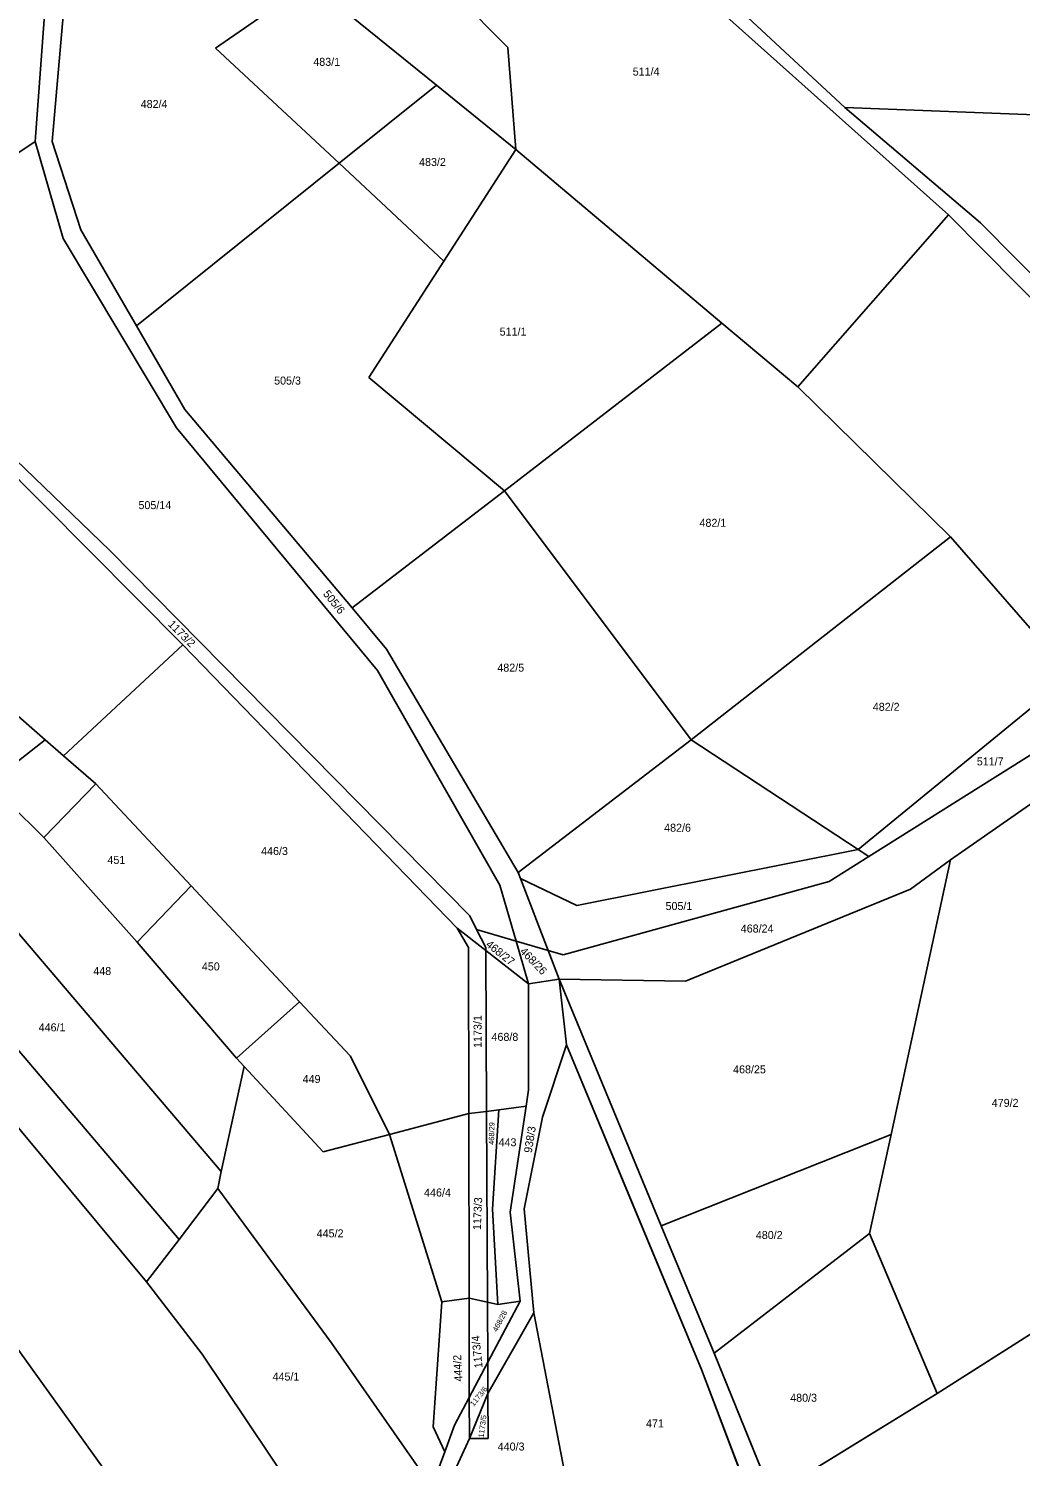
# Model space of a CAD drawing. Extents: x -593358 to -590116, y -1072518 to -1068420.
# Drawn here: x -591559.2 to -591348.6, y -1071926.1 to -1071622.8 of the extents above; entities that cross this region are included whole.
import ezdxf

# ---------------------------------------------------------------- set-up
doc = ezdxf.new("R2010")
doc.units = 0
for name, color, linetype in [('lesy', 7, 'Continuous'), ('Parcela KN', 7, 'Continuous'), ('Parcela ZE', 7, 'Continuous'), ('Parcelní číslo', 7, 'Continuous')]:
    doc.layers.add(name, color=color, linetype=linetype)

msp = doc.modelspace()

# ---------------------------------------------------------------- linework, layer by layer
at = {"layer": 'lesy'}
for points in [[(-591424.88, -1071877.07), (-591400.495, -1071867.39), (-591376.11, -1071857.71), (-591363.48, -1071799.36)], [(-591445.01, -1071838.65), (-591446.54, -1071824.7), (-591435.71, -1071850.885), (-591424.88, -1071877.07), (-591413.68, -1071904.15), (-591401.39, -1071934.26), (-591366.29, -1071912.68), (-591337.735, -1071894.515), (-591309.18, -1071876.35)], [(-591382.44, -1071994.17), (-591395.58, -1071962.26), (-591405.97, -1071934.935), (-591416.36, -1071907.61), (-591430.685, -1071873.13), (-591445.01, -1071838.65)]]:
    msp.add_lwpolyline(points, dxfattribs=at)
at = {"layer": 'Parcela KN'}
for p, q in [((-591457.44, -1071626.79), (-591488.65, -1071595.46)), ((-591411.6, -1071619.71), (-591363.88, -1071662.35)), ((-591385.94, -1071639.55), (-591408.48, -1071618.62)), ((-591455.76, -1071648.5), (-591457.44, -1071626.79)), ((-591357.12, -1071664.05), (-591385.94, -1071639.55)), ((-591471.03, -1071672.16), (-591455.76, -1071648.5)), ((-591363.88, -1071662.35), (-591275.95, -1071751.3)), ((-591338.4, -1071682.97), (-591357.12, -1071664.05)), ((-591486.97, -1071696.88), (-591471.03, -1071672.16)), ((-591526.45, -1071753.66), (-591589.09, -1071690.73)), ((-591542.01, -1071733.67), (-591587.76, -1071689.48)), ((-591458.15, -1071720.97), (-591486.97, -1071696.88)), ((-591418.58, -1071773.83), (-591458.15, -1071720.97)), ((-591465.57, -1071811.27), (-591542.01, -1071733.67)), ((-591468.22, -1071813.85), (-591526.45, -1071753.66)), ((-591332.39, -1071768.16), (-591380.82, -1071798.64)), ((-591383.05, -1071797.18), (-591418.58, -1071773.83)), ((-591329.09, -1071775.34), (-591363.48, -1071799.36)), ((-591380.82, -1071798.64), (-591383.05, -1071797.18)), ((-591380.82, -1071798.64), (-591389.26, -1071803.95)), ((-591376.11, -1071857.71), (-591363.48, -1071799.36)), ((-591389.26, -1071803.95), (-591445.72, -1071819.56)), ((-591464.12, -1071814.13), (-591465.57, -1071811.27)), ((-591534.18, -1071888.97), (-591595.89, -1071814.9)), ((-591468.22, -1071813.85), (-591465.86, -1071818)), ((-591462.16, -1071817.99), (-591464.12, -1071814.13)), ((-591455.71, -1071816.61), (-591464.12, -1071814.13)), ((-591465.86, -1071818), (-591465.79, -1071853.26)), ((-591462.16, -1071818.58), (-591462.16, -1071817.99)), ((-591448.88, -1071818.63), (-591455.71, -1071816.61)), ((-591461.99, -1071852.77), (-591462.16, -1071818.58)), ((-591445.72, -1071819.56), (-591448.88, -1071818.63)), ((-591446.54, -1071824.7), (-591453.07, -1071825.68)), ((-591453.07, -1071825.68), (-591453.07, -1071848.23)), ((-591424.88, -1071877.07), (-591446.54, -1071824.7)), ((-591445.01, -1071838.65), (-591446.54, -1071824.7)), ((-591450.12, -1071854.04), (-591445.01, -1071838.65)), ((-591416.36, -1071907.61), (-591445.01, -1071838.65)), ((-591453.07, -1071848.23), (-591453.6, -1071851.69)), ((-591453.6, -1071851.69), (-591457.01, -1071874.19)), ((-591465.79, -1071853.26), (-591465.71, -1071892.42)), ((-591461.78, -1071893.31), (-591461.99, -1071852.77)), ((-591454.01, -1071873.48), (-591450.12, -1071854.04)), ((-591376.11, -1071857.71), (-591424.88, -1071877.07)), ((-591380.65, -1071878.72), (-591376.11, -1071857.71)), ((-591457.01, -1071874.19), (-591454.86, -1071893.05)), ((-591451.95, -1071895.56), (-591454.01, -1071873.48)), ((-591413.68, -1071904.15), (-591424.88, -1071877.07)), ((-591380.65, -1071878.72), (-591413.68, -1071904.15)), ((-591366.29, -1071912.68), (-591380.65, -1071878.72)), ((-591366.29, -1071912.68), (-591309.18, -1071876.35)), ((-591522.4, -1071904.35), (-591534.18, -1071888.97)), ((-591465.71, -1071892.42), (-591465.66, -1071913.53)), ((-591461.72, -1071906.06), (-591461.78, -1071893.31)), ((-591454.86, -1071893.05), (-591461.72, -1071906.06)), ((-591451.95, -1071895.56), (-591461.69, -1071912.67)), ((-591445.06, -1071931.17), (-591451.95, -1071895.56)), ((-591500.54, -1071936.85), (-591522.4, -1071904.35)), ((-591461.69, -1071912.67), (-591461.72, -1071906.06)), ((-591413.68, -1071904.15), (-591401.39, -1071934.26)), ((-591395.58, -1071962.26), (-591416.36, -1071907.61)), ((-591465.66, -1071913.53), (-591468.78, -1071919.45)), ((-591465.66, -1071913.53), (-591465.64, -1071922.28)), ((-591461.64, -1071922.27), (-591461.69, -1071912.67)), ((-591401.39, -1071934.26), (-591366.29, -1071912.68)), ((-591468.78, -1071919.45), (-591470.88, -1071925.08)), ((-591465.64, -1071922.28), (-591469.52, -1071930.77)), ((-591465.64, -1071922.28), (-591461.64, -1071922.27)), ((-591470.88, -1071925.08), (-591473.64, -1071932.51))]:
    msp.add_line(p, q, dxfattribs=at)
at = {"layer": 'Parcela ZE'}
for p, q in [((-591526.94, -1071590.78), (-591472.61, -1071634.83)), ((-591557.81, -1071646.78), (-591554.76, -1071605.27)), ((-591554.26, -1071646.77), (-591550.51, -1071603.93)), ((-591508.37, -1071619.25), (-591519.56, -1071626.93)), ((-591519.56, -1071626.93), (-591493.29, -1071651.41)), ((-591493.29, -1071651.41), (-591472.61, -1071634.83)), ((-591472.61, -1071634.83), (-591455.76, -1071648.5)), ((-591385.94, -1071639.55), (-591335.82, -1071641.48)), ((-591567.5, -1071653.19), (-591557.81, -1071646.78)), ((-591551.9, -1071667.41), (-591557.81, -1071646.78)), ((-591548.15, -1071665.56), (-591554.26, -1071646.77)), ((-591455.76, -1071648.5), (-591412.02, -1071685.33)), ((-591536.35, -1071685.93), (-591493.29, -1071651.41)), ((-591493.29, -1071651.41), (-591471.03, -1071672.16)), ((-591363.88, -1071662.35), (-591395.87, -1071698.92)), ((-591536.35, -1071685.93), (-591548.15, -1071665.56)), ((-591527.83, -1071707.56), (-591551.9, -1071667.41)), ((-591526.04, -1071703.71), (-591536.35, -1071685.93)), ((-591458.15, -1071720.97), (-591412.02, -1071685.33)), ((-591412.02, -1071685.33), (-591395.87, -1071698.92)), ((-591395.87, -1071698.92), (-591363.45, -1071730.78)), ((-591490.56, -1071745.86), (-591526.04, -1071703.71)), ((-591485.15, -1071759.17), (-591527.83, -1071707.56)), ((-591458.15, -1071720.97), (-591490.56, -1071745.86)), ((-591418.58, -1071773.83), (-591363.45, -1071730.78)), ((-591363.45, -1071730.78), (-591337.9, -1071760.12)), ((-591483.21, -1071754.6), (-591490.56, -1071745.86)), ((-591551.83, -1071777.23), (-591526.45, -1071753.66)), ((-591455.31, -1071802.02), (-591483.21, -1071754.6)), ((-591459.17, -1071804.73), (-591485.15, -1071759.17)), ((-591383.05, -1071797.18), (-591337.9, -1071760.12)), ((-591555.7, -1071773.87), (-591563.15, -1071767.38)), ((-591601.07, -1071809.25), (-591555.7, -1071773.87)), ((-591551.83, -1071777.23), (-591555.7, -1071773.87)), ((-591455.31, -1071802.02), (-591418.58, -1071773.83)), ((-591544.95, -1071783.23), (-591551.83, -1071777.23)), ((-591555.98, -1071794.57), (-591544.95, -1071783.23)), ((-591544.95, -1071783.23), (-591524.69, -1071804.9)), ((-591563.29, -1071787.41), (-591555.98, -1071794.57)), ((-591555.98, -1071794.57), (-591536.19, -1071816.86)), ((-591442.85, -1071809.08), (-591383.05, -1071797.18)), ((-591575.84, -1071798), (-591518.32, -1071865.55)), ((-591363.48, -1071799.36), (-591371.95, -1071805.56)), ((-591454.81, -1071803.31), (-591455.31, -1071802.02)), ((-591454.81, -1071803.31), (-591442.85, -1071809.08)), ((-591448.88, -1071818.63), (-591454.81, -1071803.31)), ((-591524.69, -1071804.9), (-591536.19, -1071816.86)), ((-591524.69, -1071804.9), (-591501.69, -1071829.5)), ((-591455.71, -1071816.61), (-591459.17, -1071804.73)), ((-591371.95, -1071805.56), (-591419.74, -1071825.1)), ((-591588.11, -1071808.34), (-591527.29, -1071880)), ((-591468.22, -1071813.85), (-591462.16, -1071818.58)), ((-591536.19, -1071816.86), (-591515.1, -1071841.49)), ((-591453.07, -1071825.68), (-591455.71, -1071816.61)), ((-591462.16, -1071818.58), (-591453.07, -1071825.68)), ((-591446.54, -1071824.7), (-591448.88, -1071818.63)), ((-591419.74, -1071825.1), (-591446.54, -1071824.7)), ((-591501.69, -1071829.5), (-591515.1, -1071841.49)), ((-591501.69, -1071829.5), (-591490.88, -1071841.06)), ((-591515.1, -1071841.49), (-591513.48, -1071843.23)), ((-591490.88, -1071841.06), (-591482.61, -1071857.68)), ((-591513.48, -1071843.23), (-591518.32, -1071865.55)), ((-591513.48, -1071843.23), (-591496.67, -1071861.37)), ((-591459.37, -1071852.43), (-591453.6, -1071851.69)), ((-591482.61, -1071857.68), (-591465.79, -1071853.26)), ((-591465.79, -1071853.26), (-591461.99, -1071852.77)), ((-591461.99, -1071852.77), (-591459.37, -1071852.43)), ((-591459.37, -1071852.43), (-591460.72, -1071873.52)), ((-591496.67, -1071861.37), (-591482.61, -1071857.68)), ((-591482.61, -1071857.68), (-591471.51, -1071893.2)), ((-591518.32, -1071865.55), (-591519.07, -1071869.14)), ((-591519.07, -1071869.14), (-591527.29, -1071880)), ((-591519.07, -1071869.14), (-591495.01, -1071901.86)), ((-591499.63, -1071989.44), (-591583.79, -1071872.27)), ((-591460.72, -1071873.52), (-591459.57, -1071893.81)), ((-591527.29, -1071880), (-591534.18, -1071888.97)), ((-591471.51, -1071893.2), (-591473.31, -1071919.79)), ((-591471.51, -1071893.2), (-591465.71, -1071892.42)), ((-591465.71, -1071892.42), (-591461.78, -1071893.31)), ((-591461.78, -1071893.31), (-591459.57, -1071893.81)), ((-591459.57, -1071893.81), (-591454.86, -1071893.05)), ((-591495.01, -1071901.86), (-591473.64, -1071932.51)), ((-591465.66, -1071913.53), (-591461.72, -1071906.06)), ((-591465.64, -1071922.28), (-591461.69, -1071912.67)), ((-591473.31, -1071919.79), (-591470.88, -1071925.08))]:
    msp.add_line(p, q, dxfattribs=at)

# ---------------------------------------------------------------- texts
at = {"layer": 'Parcelní číslo'}
for s, p in [('483/1', (-591498.779, -1071630.71)), ('511/4', (-591430.954, -1071632.78)), ('482/4', (-591535.434, -1071639.67)), ('483/2', (-591476.321, -1071651.98)), ('511/1', (-591459.206, -1071688.01)), ('505/3', (-591507.101, -1071698.41)), ('505/14', (-591535.905, -1071724.86)), ('482/1', (-591416.776, -1071728.62)), ('482/5', (-591459.7, -1071759.38)), ('482/2', (-591379.977, -1071767.7)), ('511/7', (-591357.894, -1071779.29)), ('482/6', (-591424.284, -1071793.38)), ('446/3', (-591509.86, -1071798.33)), ('451', (-591542.493, -1071800.22)), ('505/1', (-591423.986, -1071810.01)), ('468/24', (-591408.013, -1071814.79)), ('450', (-591522.448, -1071822.84)), ('448', (-591545.494, -1071823.81)), ('446/1', (-591557.095, -1071835.78)), ('468/8', (-591460.94, -1071837.8)), ('449', (-591501.044, -1071846.75)), ('468/25', (-591409.64, -1071844.7)), ('479/2', (-591354.717, -1071851.82)), ('443', (-591459.441, -1071860.19)), ('446/4', (-591475.253, -1071870.86)), ('445/2', (-591498.054, -1071879.53)), ('480/2', (-591404.81, -1071879.89)), ('445/1', (-591507.432, -1071909.95)), ('480/3', (-591397.514, -1071914.45)), ('471', (-591428.126, -1071919.9)), ('440/3', (-591459.617, -1071924.81))]:
    msp.add_text(s, height=1.7, dxfattribs=at).set_placement(p)
for s, height, rotation, p in [('505/6', 1.7, 308.99614, (-591496.816, -1071742.908)), ('1173/2', 1.7, 315.01219, (-591529.769, -1071749.452)), ('468/27', 1.7, 321.25744, (-591462.292, -1071817.582)), ('468/26', 1.7, 313.92358, (-591455.039, -1071818.918)), ('1173/1', 1.7, 90.01167, (-591463.049, -1071839.295)), ('468/29', 1.14, 88.80846, (-591460.399, -1071859.891)), ('938/3', 1.7, 80.95894, (-591452.401, -1071861.699)), ('1173/3', 1.7, 87.37606, (-591463.223, -1071878.007)), ('468/28', 1.14, 62.33781, (-591459.781, -1071899.7)), ('1173/4', 1.7, 95.79854, (-591462.819, -1071907.235)), ('444/2', 1.7, 92.76187, (-591467.121, -1071910.113)), ('1173/6', 1.14, 50.76406, (-591464.723, -1071915.524)), ('1173/5', 1.14, 82.62051, (-591462.623, -1071922.121))]:
    msp.add_text(s, height=height, rotation=rotation, dxfattribs=at).set_placement(p)

doc.saveas('drawing.dxf')
